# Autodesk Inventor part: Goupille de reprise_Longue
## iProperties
Shininess: 64.0
Length Units: 11269
Angle Units: 11279
Time Units: 11290
Mass Units: 11283
Length Display Precision: 3
Angle Display Precision: 2
Compacted: True
Part Number: Goupille de reprise_Longue
Document SubType Name: Modeling
Created: 2006-01
Material: Par défaut
Designer: riri
Density: 0.0
Volumn: 0.0
Area: 0.0
PropertySet Name: Model Information
Control State: 0
Master: False
Checked Out: False
Author: riri
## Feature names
1. Base1
